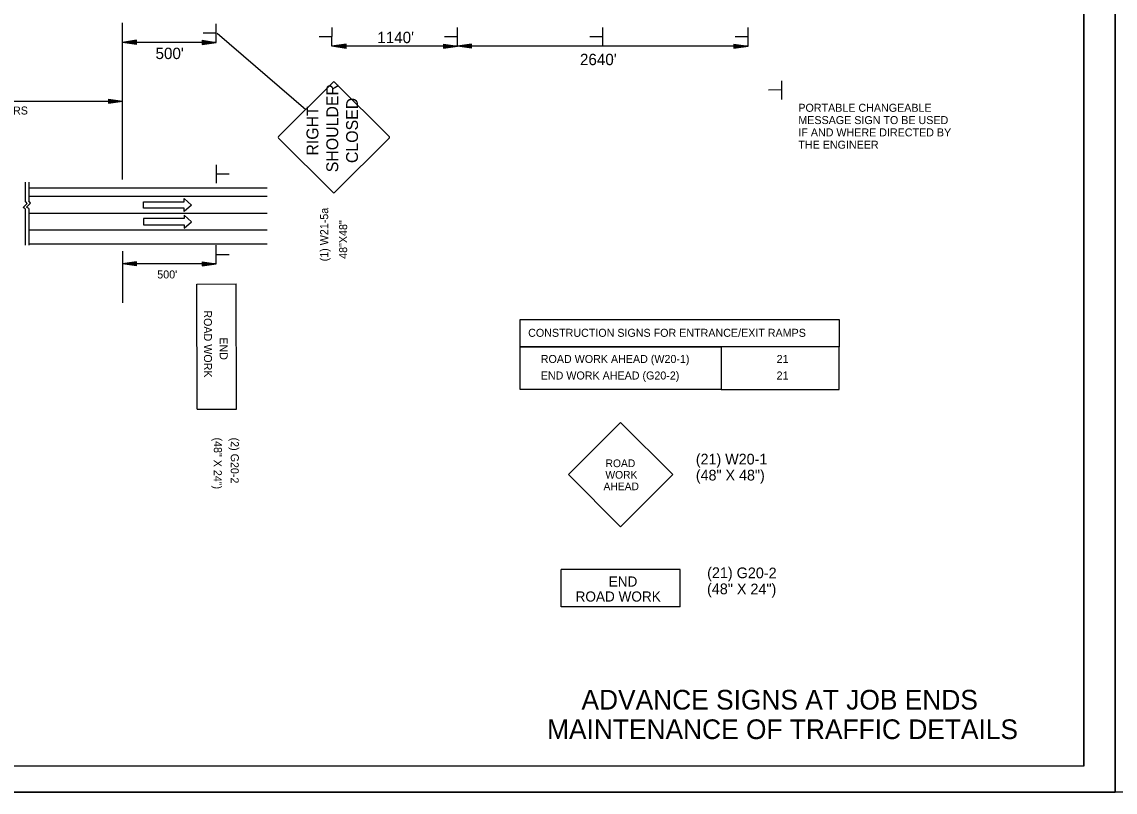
# Model space of a CAD drawing. Extents: x 13744624 to 13747958, y 3814079 to 3815145.
# Drawn here: x 13745458 to 13746291, y 3814079 to 3814666 of the extents above; entities that cross this region are included whole.
import ezdxf

# ---------------------------------------------------------------- set-up
doc = ezdxf.new("R2010")
doc.units = 0
for name, color, linetype in [('Default', 7, 'Continuous'), ('R_Border', 7, 'Continuous'), ('R_Border Notes', 7, 'Continuous'), ('R_Draft', 7, 'Continuous'), ('R_MOT', 7, 'Continuous'), ('R_No Plot', 7, 'Continuous')]:
    doc.layers.add(name, color=color, linetype=linetype)

msp = doc.modelspace()

# ---------------------------------------------------------------- linework, layer by layer
at = {"layer": 'Default'}
for p, q in [((13745534.42, 3814545.53), (13745534.42, 3814665.02)), ((13745606.67, 3814657.18), (13745674.21, 3814599.08)), ((13745605.87, 3814650.09), (13745534.44, 3814650.09)), ((13745789.73, 3814647.19), (13745694.11, 3814647.17)), ((13746011.16, 3814647.19), (13745789.73, 3814647.19)), ((13745300.84, 3814605.27), (13745534.42, 3814605.27)), ((13745462.99, 3814543.64), (13745462.99, 3814529.43)), ((13745460.41, 3814543.46), (13745460.41, 3814529.25)), ((13745644.67, 3814539.12), (13745462.99, 3814539.12)), ((13745644.67, 3814532.69), (13745462.99, 3814532.69)), ((13745460.41, 3814523.37), (13745460.41, 3814495.49)), ((13745462.99, 3814523.56), (13745462.99, 3814495.49)), ((13745644.67, 3814519.83), (13745462.99, 3814519.83)), ((13745644.67, 3814506.97), (13745462.99, 3814506.97)), ((13745644.67, 3814496.26), (13745462.99, 3814496.26)), ((13745534.42, 3814490.99), (13745534.42, 3814451.7)), ((13745605.85, 3814481.31), (13745534.42, 3814481.31))]:
    msp.add_line(p, q, dxfattribs=at)
for points in [[(13745460.41, 3814523.37), (13745458.76, 3814524.36), (13745461.71, 3814527.4), (13745460.41, 3814529.25)], [(13745462.99, 3814523.56), (13745461.34, 3814524.54), (13745464.29, 3814527.59), (13745462.99, 3814529.43)]]:
    msp.add_lwpolyline(points, dxfattribs=at)
for points in [[(13745837.39, 3814438.86), (13746080.57, 3814438.86), (13746080.57, 3814418.02), (13745837.39, 3814418.02)], [(13745837.39, 3814418.02), (13745990.77, 3814418.02), (13745990.77, 3814385.67), (13745837.39, 3814385.67)], [(13745990.77, 3814385.67), (13746080.57, 3814385.67), (13746080.57, 3814418.02), (13745990.77, 3814418.02)]]:
    msp.add_lwpolyline(points, close=True, dxfattribs=at)
at = {"layer": 'R_Border'}
for q in [(13746267.13, 3815125.92), (13744686.23, 3814098.62)]:
    msp.add_line((13746267.13, 3814098.62), q, dxfattribs=at)
at = {"layer": 'R_Draft'}
for p, q in [((13745545.15, 3814651.7), (13745534.44, 3814650.09)), ((13745545.15, 3814648.49), (13745534.44, 3814650.09)), ((13745545.15, 3814651.43), (13745536.23, 3814650.09)), ((13745545.15, 3814648.75), (13745536.23, 3814650.09)), ((13745545.15, 3814651.16), (13745538.07, 3814650.09)), ((13745545.15, 3814649.03), (13745538.07, 3814650.09)), ((13745545.15, 3814650.89), (13745539.86, 3814650.09)), ((13745545.15, 3814649.29), (13745539.86, 3814650.09)), ((13745545.15, 3814650.62), (13745541.67, 3814650.09)), ((13745545.15, 3814649.57), (13745541.67, 3814650.09)), ((13745545.15, 3814650.34), (13745543.46, 3814650.09)), ((13745545.15, 3814649.84), (13745543.46, 3814650.09)), ((13745545.15, 3814648.49), (13745545.15, 3814651.7)), ((13745595.15, 3814651.7), (13745605.87, 3814650.09)), ((13745595.15, 3814651.7), (13745595.15, 3814648.49)), ((13745595.15, 3814651.43), (13745604.08, 3814650.09)), ((13745595.15, 3814651.16), (13745602.24, 3814650.09)), ((13745595.15, 3814650.89), (13745600.45, 3814650.09)), ((13745595.15, 3814650.61), (13745598.64, 3814650.09)), ((13745595.15, 3814650.34), (13745596.85, 3814650.09)), ((13745595.15, 3814648.49), (13745605.87, 3814650.09)), ((13745595.15, 3814649.57), (13745598.64, 3814650.09)), ((13745595.15, 3814649.03), (13745602.24, 3814650.09)), ((13745595.15, 3814648.75), (13745604.08, 3814650.09)), ((13745595.15, 3814649.29), (13745600.45, 3814650.09)), ((13745595.15, 3814649.84), (13745596.85, 3814650.09)), ((13745704.83, 3814648.77), (13745694.11, 3814647.17)), ((13745704.83, 3814645.56), (13745694.11, 3814647.17)), ((13745704.83, 3814648.5), (13745695.9, 3814647.17)), ((13745704.83, 3814645.83), (13745695.9, 3814647.17)), ((13745704.83, 3814648.23), (13745697.75, 3814647.17)), ((13745704.83, 3814646.1), (13745697.75, 3814647.17)), ((13745704.83, 3814647.96), (13745699.53, 3814647.17)), ((13745704.83, 3814646.37), (13745699.53, 3814647.17)), ((13745704.83, 3814647.69), (13745701.35, 3814647.17)), ((13745704.83, 3814646.65), (13745701.35, 3814647.17)), ((13745704.83, 3814647.42), (13745703.14, 3814647.17)), ((13745704.83, 3814646.91), (13745703.14, 3814647.17)), ((13745704.83, 3814645.56), (13745704.83, 3814648.77)), ((13745779.01, 3814648.8), (13745789.73, 3814647.19)), ((13745779.01, 3814648.8), (13745779.01, 3814645.59)), ((13745779.01, 3814648.53), (13745787.94, 3814647.19)), ((13745779.01, 3814648.26), (13745786.1, 3814647.19)), ((13745779.01, 3814647.99), (13745784.31, 3814647.19)), ((13745779.01, 3814647.71), (13745782.5, 3814647.19)), ((13745779.01, 3814647.45), (13745780.71, 3814647.19)), ((13745779.01, 3814645.59), (13745789.73, 3814647.19)), ((13745779.01, 3814646.67), (13745782.5, 3814647.19)), ((13745779.01, 3814646.13), (13745786.1, 3814647.19)), ((13745779.01, 3814645.85), (13745787.94, 3814647.19)), ((13745779.01, 3814646.4), (13745784.31, 3814647.19)), ((13745779.01, 3814646.94), (13745780.71, 3814647.19)), ((13745800.44, 3814648.8), (13745789.73, 3814647.19)), ((13745800.44, 3814645.59), (13745789.73, 3814647.19)), ((13745800.44, 3814648.53), (13745791.52, 3814647.19)), ((13745800.44, 3814645.85), (13745791.52, 3814647.19)), ((13745800.44, 3814648.26), (13745793.36, 3814647.19)), ((13745800.44, 3814646.13), (13745793.36, 3814647.19)), ((13745800.44, 3814647.99), (13745795.15, 3814647.19)), ((13745800.44, 3814646.4), (13745795.15, 3814647.19)), ((13745800.44, 3814647.72), (13745796.96, 3814647.19)), ((13745800.44, 3814646.67), (13745796.96, 3814647.19)), ((13745800.44, 3814647.45), (13745798.75, 3814647.19)), ((13745800.44, 3814646.94), (13745798.75, 3814647.19)), ((13745800.44, 3814645.59), (13745800.44, 3814648.8)), ((13746000.44, 3814648.8), (13746011.16, 3814647.19)), ((13746000.44, 3814648.8), (13746000.44, 3814645.59)), ((13746000.44, 3814648.53), (13746009.37, 3814647.19)), ((13746000.44, 3814648.26), (13746007.53, 3814647.19)), ((13746000.44, 3814647.99), (13746005.74, 3814647.19)), ((13746000.44, 3814647.71), (13746003.93, 3814647.19)), ((13746000.44, 3814647.45), (13746002.14, 3814647.19)), ((13746000.44, 3814645.59), (13746011.16, 3814647.19)), ((13746000.44, 3814646.67), (13746003.93, 3814647.19)), ((13746000.44, 3814646.13), (13746007.53, 3814647.19)), ((13746000.44, 3814645.85), (13746009.37, 3814647.19)), ((13746000.44, 3814646.4), (13746005.74, 3814647.19)), ((13746000.44, 3814646.94), (13746002.14, 3814647.19)), ((13745653.42, 3814578.28), (13745695, 3814619.87)), ((13745696.07, 3814619.87), (13745737.66, 3814578.28)), ((13745523.71, 3814606.88), (13745534.42, 3814605.27)), ((13745523.71, 3814606.88), (13745523.71, 3814603.67)), ((13745523.71, 3814606.61), (13745532.63, 3814605.27)), ((13745523.71, 3814606.34), (13745530.79, 3814605.27)), ((13745523.71, 3814606.07), (13745529.01, 3814605.27)), ((13745523.71, 3814605.79), (13745527.19, 3814605.27)), ((13745523.71, 3814605.52), (13745525.4, 3814605.27)), ((13745523.71, 3814603.67), (13745534.42, 3814605.27)), ((13745523.71, 3814604.75), (13745527.19, 3814605.27)), ((13745523.71, 3814604.21), (13745530.79, 3814605.27)), ((13745523.71, 3814603.93), (13745532.63, 3814605.27)), ((13745523.71, 3814604.47), (13745529.01, 3814605.27)), ((13745523.71, 3814605.02), (13745525.4, 3814605.27)), ((13745695, 3814535.63), (13745653.42, 3814577.22)), ((13745737.66, 3814577.22), (13745696.07, 3814535.63)), ((13745545.14, 3814482.92), (13745534.42, 3814481.31)), ((13745545.14, 3814479.71), (13745534.42, 3814481.31)), ((13745545.14, 3814482.65), (13745536.21, 3814481.31)), ((13745545.14, 3814479.97), (13745536.21, 3814481.31)), ((13745545.14, 3814482.38), (13745538.06, 3814481.31)), ((13745545.14, 3814480.25), (13745538.06, 3814481.31)), ((13745545.14, 3814482.11), (13745539.84, 3814481.31)), ((13745545.14, 3814480.52), (13745539.84, 3814481.31)), ((13745545.14, 3814481.84), (13745541.66, 3814481.31)), ((13745545.14, 3814480.79), (13745541.66, 3814481.31)), ((13745545.14, 3814481.57), (13745543.45, 3814481.31)), ((13745545.14, 3814481.06), (13745543.45, 3814481.31)), ((13745545.14, 3814479.71), (13745545.14, 3814482.92)), ((13745595.14, 3814482.92), (13745605.85, 3814481.31)), ((13745595.14, 3814482.92), (13745595.14, 3814479.71)), ((13745595.14, 3814482.65), (13745604.06, 3814481.31)), ((13745595.14, 3814482.38), (13745602.22, 3814481.31)), ((13745595.14, 3814482.11), (13745600.44, 3814481.31)), ((13745595.14, 3814481.83), (13745598.62, 3814481.31)), ((13745595.14, 3814481.57), (13745596.83, 3814481.31)), ((13745595.14, 3814479.71), (13745605.85, 3814481.31)), ((13745595.14, 3814480.79), (13745598.62, 3814481.31)), ((13745595.14, 3814480.25), (13745602.22, 3814481.31)), ((13745595.14, 3814479.97), (13745604.06, 3814481.31)), ((13745595.14, 3814480.52), (13745600.44, 3814481.31)), ((13745595.14, 3814481.06), (13745596.83, 3814481.31))]:
    msp.add_line(p, q, dxfattribs=at)
for centre, start, end in [((13745695.54, 3814619.34), 45.00009, 135), ((13745653.95, 3814577.75), 135, 225), ((13745737.12, 3814577.75), 314.99991, 45.00008), ((13745695.54, 3814536.16), 225, 314.99992)]:
    msp.add_arc(centre, 0.754, start, end, dxfattribs=at)
at = {"layer": 'R_MOT'}
for p, q in [((13745605.87, 3814650.09), (13745605.93, 3814664.27)), ((13745694.11, 3814647.22), (13745694.18, 3814661.4)), ((13745789.73, 3814647.19), (13745789.79, 3814661.38)), ((13745900.44, 3814647.19), (13745900.51, 3814661.38)), ((13746011.16, 3814647.19), (13746011.22, 3814661.38)), ((13745605.9, 3814657.15), (13745596.01, 3814657.19)), ((13745694.15, 3814654.28), (13745684.26, 3814654.32)), ((13745789.76, 3814654.25), (13745779.87, 3814654.29)), ((13745900.48, 3814654.25), (13745890.59, 3814654.29)), ((13746011.19, 3814654.25), (13746001.3, 3814654.29)), ((13746036.65, 3814620.89), (13746036.71, 3814606.71)), ((13746036.68, 3814613.84), (13746026.8, 3814613.79)), ((13745605.85, 3814556.92), (13745605.79, 3814542.74)), ((13745605.82, 3814549.86), (13745615.71, 3814549.82)), ((13745550.36, 3814528.68), (13745581.53, 3814528.68)), ((13745550.36, 3814523.69), (13745550.36, 3814528.68)), ((13745581.53, 3814528.68), (13745581.53, 3814531.17)), ((13745581.53, 3814531.17), (13745587, 3814526.18)), ((13745581.53, 3814523.69), (13745550.36, 3814523.69)), ((13745587, 3814526.18), (13745581.53, 3814521.19)), ((13745581.53, 3814521.19), (13745581.53, 3814523.69)), ((13745581.53, 3814515.97), (13745550.36, 3814515.97)), ((13745550.36, 3814515.97), (13745550.36, 3814510.98)), ((13745550.36, 3814510.98), (13745581.53, 3814510.98)), ((13745587, 3814513.48), (13745581.53, 3814518.47)), ((13745581.53, 3814518.47), (13745581.53, 3814515.97)), ((13745581.53, 3814508.49), (13745587, 3814513.48)), ((13745581.53, 3814510.98), (13745581.53, 3814508.49)), ((13745605.85, 3814481.31), (13745605.79, 3814495.5)), ((13745605.82, 3814488.37), (13745615.71, 3814488.41)), ((13745591.2, 3814465.94), (13745621.16, 3814465.99)), ((13745591.36, 3814370.58), (13745591.2, 3814465.94)), ((13745621.33, 3814370.63), (13745621.16, 3814465.99)), ((13745591.36, 3814370.58), (13745621.33, 3814370.64)), ((13745914.08, 3814360.53), (13745874.29, 3814320.74)), ((13745953.87, 3814320.74), (13745914.08, 3814360.53)), ((13745914.08, 3814280.98), (13745874.29, 3814320.74)), ((13745953.87, 3814320.74), (13745914.08, 3814280.98)), ((13745868.78, 3814219.91), (13745868.78, 3814248.38)), ((13745959.37, 3814248.37), (13745868.79, 3814248.38)), ((13745959.37, 3814219.91), (13745959.37, 3814248.38)), ((13745959.37, 3814219.91), (13745868.78, 3814219.91))]:
    msp.add_line(p, q, dxfattribs=at)
at = {"layer": 'R_No Plot'}
msp.add_line((13744624.22, 3814078.73), (13746290.89, 3814078.73), dxfattribs=at)
for points in [[(13744624.19, 3815145.39), (13746290.89, 3815145.39), (13746290.89, 3814078.71), (13744624.19, 3814078.71)], [(13746290.89, 3815145.39), (13747957.59, 3815145.39), (13747957.59, 3814078.71), (13746290.89, 3814078.71)], [(13745855.83, 3815125.92), (13745953.93, 3815125.92), (13745953.93, 3815076.52), (13746034.49, 3815076.52), (13746150.48, 3815076.52), (13746150.48, 3814954.86), (13746267.13, 3814954.86), (13746267.13, 3814098.62), (13744686.23, 3814098.62), (13744686.23, 3815125.92)]]:
    msp.add_lwpolyline(points, close=True, dxfattribs=at)

# ---------------------------------------------------------------- texts
at = {"layer": 'Default'}
for s, height, p in [("1140'", 8.664, (13745728.62, 3814649.57)), ("500'", 8.664, (13745559.65, 3814637.41)), ("2640'", 8.664, (13745883.08, 3814632.76)), ('PORTABLE CHANGEABLE', 6.1, (13746049.51, 3814597.23)), ('LANE CLOSURE TAPERS', 6.1, (13745364.46, 3814595.15)), ('MESSAGE SIGN TO BE USED', 6.1, (13746049.51, 3814587.85)), ('IF AND WHERE DIRECTED BY', 6.1, (13746049.51, 3814578.46)), ('THE ENGINEER', 6.1, (13746049.51, 3814569.08)), ("500'", 6.1, (13745560.98, 3814470.2)), ('CONSTRUCTION SIGNS FOR ENTRANCE/EXIT RAMPS', 6.1, (13745843.6, 3814425.72)), ('ROAD WORK AHEAD (W20-1)', 6.1, (13745853.22, 3814405.78)), ('21', 6.1, (13746032.93, 3814405.78)), ('END WORK AHEAD (G20-2)', 6.1, (13745853.22, 3814393.19)), ('21', 6.1, (13746032.93, 3814393.19))]:
    msp.add_text(s, height=height, dxfattribs=at).set_placement(p)
at = {"layer": 'R_Border Notes'}
for s, p in [('ADVANCE SIGNS AT JOB ENDS', (13745884.25, 3814141.64)), ('MAINTENANCE OF TRAFFIC DETAILS', (13745858.03, 3814119.14))]:
    msp.add_text(s, height=15, dxfattribs=at).set_placement(p)
at = {"layer": 'R_Draft'}
for s, height, p in [('SHOULDER', 9.048, (13745698.85, 3814551.13)), ('CLOSED', 9.048, (13745713.93, 3814558.13)), ('RIGHT', 9.048, (13745683.77, 3814563.83)), ('(1) W21-5a', 6.104, (13745691.21, 3814483.26)), ('48"X48"', 6.104, (13745705.67, 3814485.16))]:
    msp.add_text(s, height=height, rotation=90, dxfattribs=at).set_placement(p)
at = {"layer": 'R_MOT'}
for s, height, rotation, p in [('ROAD WORK', 6.1, 270.09919, (13745596.49, 3814445.9)), ('END', 6.1, 270.09919, (13745608.54, 3814425.35)), ('(48" X 24")', 6.1, 269.79128, (13745604.13, 3814348.97)), ('(2) G20-2', 6.1, 269.79128, (13745617.05, 3814348.92)), ('(21) W20-1', 8.143, 359.99883, (13745971.38, 3814328.43)), ('ROAD', 5.862, 359.99927, (13745902.59, 3814326.41)), ('WORK', 5.861, 359.99886, (13745902.47, 3814317.61)), ('(48" X 48")', 8.1429, 359.99883, (13745971.38, 3814316.22)), ('AHEAD', 5.862, 359.99939, (13745901.04, 3814308.82)), ('(21) G20-2', 8.184, 359.69136, (13745979.98, 3814241.89)), ('END', 7.733, 359.99928, (13745904.99, 3814235.35)), ('(48" X 24")', 8.1836, 359.69136, (13745979.91, 3814229.62)), ('ROAD WORK', 7.733, 359.99928, (13745879.75, 3814223.93))]:
    msp.add_text(s, height=height, rotation=rotation, dxfattribs=at).set_placement(p)

doc.saveas('drawing.dxf')
